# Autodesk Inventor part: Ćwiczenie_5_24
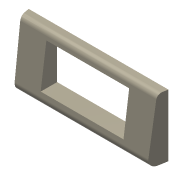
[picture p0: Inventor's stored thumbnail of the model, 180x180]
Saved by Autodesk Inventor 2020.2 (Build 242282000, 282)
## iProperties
Created: 2005-03
Part Number: Ćwiczenie_5_24
Document SubType Name: Modeling
Designer: F.Stasiak
Manufacturer: Standard
Standards Organization: Custom
Density: 1 g/cm^3
Material: Ogólny
Appearance: Jasnobeżowa
Manager: www.cadconsulting.pl
Company: Fabian Stasiak CAD Consulting
Author: F.Stasiak
Subject: Zbiór ćwiczeń. Autodesk Inventor 2020. Kurs podstawowy
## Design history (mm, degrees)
sketch "Szkic2"
  geometry: L1 (0, 0)-(0, 60); L2 (0, 60)-(-10, 60); L3 (-19.907, 51.361)-(-32.861, -42.959); L4 (-18, -60)-(0, -60); L5 (0, -60)-(0, 0); A1 r 10 centre (-10, 50) between (-10, 60) and (-19.907, 51.361); A2 r 15 centre (-18, -45) between (-32.861, -42.959) and (-18, -60)
  constraints: 10 end point, 4 point on circle, 4 tangent, 2 centre point, 2 collinear, 1 parallel, 1 perpendicular
  dimensions: "d0" = 120 distance between parallel lines of L2 L4; "d1" = 15 radius of A2; "d2" = 10 radius of A1; "d3" = 18 distance of L4.start L4.end; "d4" = 10 distance of L1.end L2.end
extrude "Wyciągnięcie proste1" new body sketch "Szkic2" stored distance "d5" = 270; taper "d6" = 0 deg
feature "Szkic powierzchni1" dims angle "d7" = 10 deg
node "Płaszczyzna konstrukcyjna1"
sketch "Szkic4"
  geometry: L1 (80, 90)-(-80, 90); L2 (-80, 90)-(-80, 10); L3 (-80, 10)-(80, 10); L4 (80, 10)-(80, 90); L5 (0, 90)-(0, 10); 1 further point
  constraints: 10 end point, 2 midpoint, 2 parallel, 1 horizontal, 1 perpendicular, 1 point on line
  dimensions: "d17" = 160 distance of L2.end L3.end; "d18" = 80 distance of L1.end L2.end; "d19" = 35 distance from line of point (0, 45) L3
extrude "Wyciągnięcie proste2" cut sketch "Szkic4" extent not by distance; stored distance "d20" = 250; taper "d21" = 0 deg
node "Bryła1"
node "Korpusy bryłowe"
node "Korpusy powierzchniowe"
